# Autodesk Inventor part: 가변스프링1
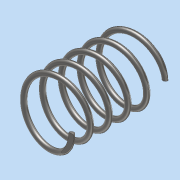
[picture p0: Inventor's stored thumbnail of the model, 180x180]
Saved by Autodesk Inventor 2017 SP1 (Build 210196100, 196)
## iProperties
Part Number: 가변스프링1
Material: 강철, 연강
Document SubType Name: Modeling
Designer: MRC
Density: 7.85 g/cm^3
Appearance: 반연마
Mass: 8.42324 g
Surface Area: 21.7217 cm^2
Volume: 1.07302 cm^3
Author: MRC
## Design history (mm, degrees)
sketch "스케치1"
  geometry: L1 (0, 0)-(0, 36.411); L2 (0, 0)-(11, 0); L3 (0, 36.411)-(11, 36.411); C1 r 1 at (11, 0)
  constraints: 6 end point, 2 horizontal, 1 centre point, 1 coincident, 1 vertical
  dimensions: "d0" = 36.4112 distance of L1.start L1.end (derived); "d1" = 2 diameter of C1; "d2" = 22 diameter of L2.end L1
feature "코일1" sketch "스케치1" pitch "d3" = 10; turns "d5" = 5; dims "d4" = 36.4112 (= d0), "d6" = 0, angle "d7" = 90 deg, angle "d8" = 90 deg, "d9" = 0, "d10" = 0
sketch "스케치2"
  geometry: L1 (15, 0)-(-15, 0); L2 (-15, 0)-(-15, 36.411); L3 (-15, 36.411)-(15, 36.411); L4 (15, 36.411)-(15, 0); 1 further point
  constraints: 8 end point, 2 parallel, 1 horizontal, 1 midpoint, 1 perpendicular
  dimensions: "d11" = 36.4112 distance of L3.end L1.start (= d0); "d12" = 30 distance between parallel lines of L2 L4; "d13" = 15 distance from line of point (0, 0) L4 (= 0.5 x d12)
extrude "돌출1" sketch "스케치2" stored distance "d14" = 30; taper "d15" = 0 deg
node "솔리드1"
